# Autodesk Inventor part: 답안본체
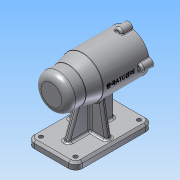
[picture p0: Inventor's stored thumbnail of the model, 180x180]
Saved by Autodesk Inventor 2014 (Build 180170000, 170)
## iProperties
Created: 2019-07
Part Number: 답안본체
Material: 알루미늄 6061
Document SubType Name: Modeling
Designer: net
Density: 2.71 g/cm^3
Appearance: 알루미늄 - 평지
Mass: 650.659 g
Surface Area: 656.887 cm^2
Volume: 240.096 cm^3
Author: net
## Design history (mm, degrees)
sketch "스케치1"
  geometry: L1 (-56, 0)-(56, 0); L2 (56, 21)-(56, 30); L3 (56, 30)-(-11, 30); L4 (-56, 0)-(-56, 15); L5 (-46, 25)-(-31, 25); L6 (-31, 25)-(-11, 30); L7 (56, 21)-(41, 21); L8 (41, 21)-(41, 21); L9 (38, 24)-(-10, 24); L10 (-13, 21)-(-13, 21); L11 (-13, 21)-(-24.7, 21); L12 (-25, 20.7)-(-25, 17.5); L13 (-25, 17.5)-(-42.7, 17.5); L14 (-43, 17.2)-(-43, 16); L15 (-43, 16)-(-46.7, 16); L16 (-47, 15.7)-(-47, 10.5); L17 (-47, 10.5)-(-47, 10.5); L18 (-50, 7.5)-(-50, 0); A1 r 10 centre (-46, 15) between (-46, 25) and (-56, 15); A2 r 3 centre (-47, 7.5) between (-47, 10.5) and (-50, 7.5); A3 r 3 centre (-10, 21) between (-10, 24) and (-13, 21); A4 r 3 centre (38, 21) between (41, 21) and (38, 24); A5 r 0.3 centre (-46.7, 15.7) between (-46.7, 16) and (-47, 15.7); A6 r 0.3 centre (-42.7, 17.2) between (-42.7, 17.5) and (-43, 17.2); A7 r 0.3 centre (-24.7, 20.7) between (-24.7, 21) and (-25, 20.7); 9 further points
  constraints: 36 end point, 15 perpendicular, 15 point on line, 14 point on circle, 14 tangent, 7 centre point, 4 equal radius, 1 coincident, 1 horizontal, 1 midpoint, 1 parallel
  dimensions: "d0" = 112 distance of L1.start L1.end; "d1" = 42 diameter of L2.start L1; "d2" = 60 diameter of L2.end L1; "d3" = 67 distance of L2.end L3.end; "d4" = 25 distance of L1.start point (-56, 25); "d5" = 25 distance of point (-56, 25) L5.end; "d6" = 45 horizontal distance of point (-56, 25) L3.end; "d7" = 10 radius of A1; "d8" = 15 distance of L2.start L7.end; "d9" = 48 diameter of point (41, 24) L1; "d10" = 54 distance of point (41, 24) point (-13, 24); "d11" = 42 diameter of L10.end L1; "d12" = 12 distance of L10.end point (-25, 21); "d13" = 35 diameter of L12.end L1; "d14" = 18 distance of L12.end point (-43, 17.5); "d15" = 32 diameter of L14.end L1; "d16" = 4 distance of L14.end point (-47, 16); "d17" = 21 diameter of L16.end L1; "d18" = 3 distance of L16.end point (-50, 10.5); "d19" = 3 radius of A2; "d20" = 0.3 radius of A5
revolve "회전1" sketch "스케치1" stored, may be unused: angle "d21" = 90 deg
node "작업 평면1"
sketch "스케치2"
  geometry: C1 r 21 at (0, 0) reference; A1 r 30 centre (0, 0) between (0, 30) and (-5.97, 29.4) reference; A2 r 6 centre (0, 30) between (5.97, 29.4) and (-5.97, 29.4); 2 further points
  constraints: 5 point on circle, 2 vertical alignment, 1 centre point, 1 coincident, 2 other
  dimensions: "d23" = 12 diameter of A2
extrude "돌출1" join sketch "스케치2" distance "d24" = 16; taper "d25" = 0 deg
fillet "모깎기1" dims "d29" = 3
fillet "모깎기2" dims "d30" = 1
node "작업 평면2"
sketch "스케치3"
  geometry: L1 (35, -56)-(-35, -56); L2 (-35, -56)-(-35, 56); L3 (-35, 56)-(35, 56); L4 (35, 56)-(35, -56); L5 (35, -56)-(-35, 56); L6 (-35, -56)-(35, 56); 1 further point
  constraints: 12 end point, 2 midpoint, 2 parallel, 1 horizontal, 1 perpendicular
  dimensions: "d32" = 70 distance of L2.end L3.end; "d33" = 112 distance of L1.end L2.end
extrude "돌출2" join sketch "스케치3" distance "d34" = 10; taper "d35" = 0 deg
fillet "모깎기3" dims "d36" = 10
chamfer "모따기1" distance "d37" = 3; stored, may be unused: second distance "d38" = 2, angle "d39" = 45 deg
sketch "스케치4"
  geometry: L1 (25, -53)-(-25, -53) reference; L2 (-4, 31)-(-4, -36); L3 (-4, -36)-(4, -36); L4 (4, -36)-(4, 31); L5 (4, 31)-(-4, 31); L6 (-25, 56)-(25, 56) reference; L7 (-25, -56)-(25, -56) reference; L8 (-28, 4)-(28, 4); L9 (28, 4)-(28, -4); L10 (28, -4)-(-28, -4); L11 (-28, -4)-(-28, 4); L12 (35, -46)-(35, 46) reference; L13 (-35, 46)-(-35, -46) reference; 3 further points
  constraints: 16 end point, 5 parallel, 3 perpendicular, 2 midpoint, 1 horizontal alignment, 1 vertical alignment
  dimensions: "d40" = 25 distance between parallel lines of L6 L5; "d41" = 20 distance between parallel lines of L7 L3; "d42" = 8 distance between parallel lines of L2 L4; "d43" = 7 distance between parallel lines of L12 L9; "d44" = 7 distance between parallel lines of L13 L11; "d45" = 8 distance between parallel lines of L8 L10
extrude "돌출3" join sketch "스케치4" stored distance "d46" = 10; taper "d47" = 0 deg
feature "면 기울기1" dims angle "d48" = 10 deg
feature "면 기울기2" dims angle "d49" = 10 deg
feature "면 기울기3" dims angle "d50" = 20 deg
fillet "모깎기4" dims "d51" = 3
fillet "모깎기5" dims "d52" = 3
fillet "모깎기6" dims "d53" = 3
sketch "스케치5"
  geometry: C1 r 3 at (-25, 46); C2 r 3 at (25, 46); C3 r 3 at (25, -46); C4 r 3 at (-25, -46); A1 r 7 centre (25, 46) between (32, 46) and (25, 53) reference; A2 r 7 centre (-25, 46) between (-25, 53) and (-32, 46) reference; A3 r 7 centre (-25, -46) between (-32, -46) and (-25, -53) reference; A4 r 7 centre (25, -46) between (25, -53) and (32, -46) reference; 1 further point
  constraints: 4 centre point, 4 coincident
  dimensions: "d54" = 6 diameter of C1; "d55" = 6 diameter of C2; "d56" = 6 diameter of C3; "d57" = 6 diameter of C4
extrude "돌출4" cut sketch "스케치5" distance "d58" = 10; taper "d59" = 0 deg
fillet "모깎기7" dims "d60" = 3
chamfer "모따기2" distance "d61" = 1; stored, may be unused: second distance "d62" = 2, angle "d63" = 45 deg
sketch "스케치6"
  geometry: A1 r 6 centre (30, -30) between (30.171, -35.998) and (30.171, -24.002) reference; A2 r 6 centre (0, 0) between (5.998, 0.171) and (-5.998, 0.171) reference; A3 r 6 centre (-30, -30) between (-30.171, -24.002) and (-30.171, -35.998) reference; A4 r 6 centre (0, -60) between (-5.998, -60.171) and (5.998, -60.171) reference; 4 further points
  constraints: 4 coincident
hole "구멍1" sketch "스케치6" at (0, 0), (30, -30), (0, -60), (-30, -30) diameter "d64" = 3.242; stored, may be unused: countersink angle "d68" = 90 deg, drill point angle "d70" = 118 deg; dims "d65" = 8, "d66" = 4, "d67" = 2, "d69" = 11
node "작업 평면3"
sketch "스케치7"
  geometry: L1 (33.5, 30.171)-(33.5, 36) reference; 2 further points
  constraints: 1 horizontal alignment, 1 other
  dimensions: "d71" = 42 distance from line of L1 point (-8.5, 0)
feature "엠보싱1" sketch "스케치7" dims "d0" = 112, "d1" = 42, "d2" = 60, "d3" = 67, "d4" = 25, "d5" = 25, "d6" = 45, "d7" = 10, "d8" = 15, "d9" = 48, "d10" = 54, "d11" = 42, "d12" = 12, "d13" = 35, "d14" = 18, "d15" = 32, "d16" = 4, "d17" = 21, "d18" = 3, "d19" = 3, "d20" = 0.3, "d72" = 0.5, "d73" = 0
node "솔리드1"
pattern_circular "원형 패턴1" dims angle "d27" = 360 deg
node "투영된 루프1"
other parameters: "d22" = 56
